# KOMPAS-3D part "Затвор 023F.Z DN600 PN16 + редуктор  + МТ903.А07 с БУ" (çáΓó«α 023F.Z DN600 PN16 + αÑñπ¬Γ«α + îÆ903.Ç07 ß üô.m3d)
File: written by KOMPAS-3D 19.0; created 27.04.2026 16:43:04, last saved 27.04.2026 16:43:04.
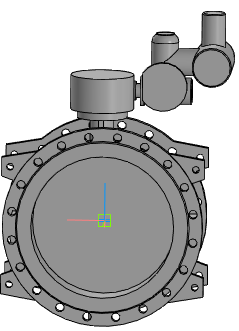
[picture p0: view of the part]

Document properties: Полное имя файла: ..\..\Затвор 023F.Z DN400-DN1600 + редуктор + МТ903\Затвор 023F.Z DN600 PN16 + редуктор + МТ903.А07 с БУ.a3d

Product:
- Part/product: Затвор 023F.Z DN600 PN16 + редуктор  + МТ903.А07 с БУ
    Масса: 591.604

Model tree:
1. Операция без истории:1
